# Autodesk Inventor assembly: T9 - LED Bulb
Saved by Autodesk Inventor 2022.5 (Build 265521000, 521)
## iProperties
Created: 2024-07
Part Number: T9 - LED Bulb
Document SubType Name: Assembly
Designer: AdminForWorker
Title: T9 - LED Bulb
Author: AdminForWorker
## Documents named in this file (3)
- c:\worker\convert-fusion-r03-cosv3\tmp\job-1\30\temp\files\365bae9e-e80c-4fba-9af5-331234e5ea32\T9 - LED Bulb.iam
- c:\worker\convert-fusion-r03-cosv3\tmp\job-1\30\temp\files\365bae9e-e80c-4fba-9af5-331234e5ea32\T9.ipt
- c:\worker\convert-fusion-r03-cosv3\tmp\job-1\30\temp\files\365bae9e-e80c-4fba-9af5-331234e5ea32\E26 Base.ipt
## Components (2 placed, 2 different names)
1. T9:1
2. E26 Base:1
